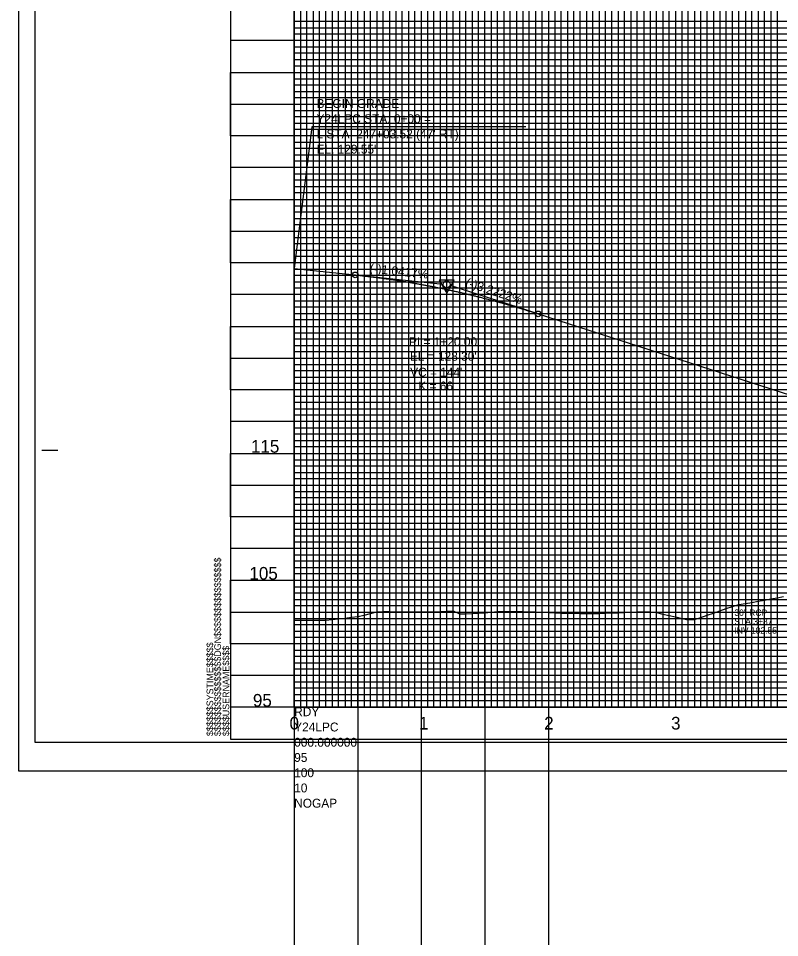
# Model space of a CAD drawing. Extents: x 2345490 to 2436403, y 465165 to 573888.
# Drawn here: x 2410678 to 2411277, y 523025 to 523748 of the extents above; entities that cross this region are included whole.
import ezdxf

# ---------------------------------------------------------------- set-up
doc = ezdxf.new("R2010")
doc.units = 0
for name, color, linetype in [('Old_Level_1', 7, 'Continuous'), ('Old_Level_18', 7, 'Continuous'), ('Old_Level_2', 7, 'Continuous'), ('Old_Level_3', 7, 'Continuous'), ('Old_Level_40', 7, 'Continuous'), ('Old_Level_41', 7, 'Continuous'), ('Old_Level_42', 7, 'Continuous'), ('Old_Level_43', 7, 'Continuous'), ('Old_Level_50', 7, 'Continuous'), ('Old_Level_51', 7, 'Continuous'), ('Old_Level_52', 7, 'Continuous'), ('Old_Level_62', 7, 'Continuous'), ('Old_Level_63', 7, 'Continuous')]:
    doc.layers.add(name, color=color, linetype=linetype)

msp = doc.modelspace()

# ---------------------------------------------------------------- linework, layer by layer
at = {"layer": 'Old_Level_1'}
msp.add_lwpolyline([(2410895.325, 523274.6675), (2410900.325, 523274.6325), (2410905.325, 523274.59725), (2410910.325, 523274.56125), (2410915.325, 523274.5245), (2410920.325, 523274.53525), (2410925.325, 523275.05275), (2410930.325, 523275.65025), (2410935.325, 523276.24575), (2410940.325, 523276.839), (2410945.325, 523277.4295), (2410950.325, 523278.501), (2410955.325, 523279.87925), (2410960.325, 523281.09575), (2410965.325, 523281.2845), (2410970.325, 523281.28375), (2410975.325, 523281.26525), (2410980.325, 523281.25025), (2410985.325, 523281.23875), (2410990.325, 523281.23125), (2410995.325, 523281.22775), (2411000.325, 523281.2285), (2411005.325, 523281.23375), (2411010.325, 523281.31075), (2411015.325, 523281.62125), (2411020.325, 523281.93025), (2411025.325, 523279.56475), (2411030.325, 523279.48925), (2411035.325, 523279.77975), (2411040.325, 523280.10525), (2411045.325, 523280.4675), (2411050.325, 523280.867), (2411055.325, 523281.3055), (2411060.325, 523281.60625), (2411065.325, 523281.5265), (2411070.325, 523281.44175), (2411075.325, 523281.3515), (2411080.325, 523281.24825), (2411085.325, 523281.04375), (2411090.325, 523280.8345), (2411095.325, 523280.62025), (2411100.325, 523280.401), (2411105.325, 523280.17675), (2411110.325, 523280.058), (2411115.325, 523280.009), (2411120.325, 523279.95725), (2411125.325, 523279.90275), (2411130.325, 523279.8455), (2411135.325, 523279.7855), (2411140.325, 523279.97425), (2411145.325, 523280.24075), (2411150.325, 523280.4725), (2411155.325, 523280.71125), (2411160.325, 523280.95725), (2411165.325, 523281.2105), (2411170.325, 523281.39525), (2411175.325, 523281.234), (2411180.325, 523280.5065), (2411185.325, 523279.378), (2411190.325, 523278.26325), (2411195.325, 523277.163), (2411200.325, 523276.01325), (2411205.325, 523274.81025), (2411210.325, 523275.07525), (2411215.325, 523276.74475), (2411220.325, 523278.4395), (2411225.325, 523280.15925), (2411230.325, 523281.90325), (2411235.325, 523283.67075), (2411240.325, 523285.4615), (2411245.325, 523286.84525), (2411250.325, 523287.71675), (2411255.325, 523288.597), (2411260.325, 523289.48575), (2411265.325, 523290.38325), (2411270.325, 523291.28875), (2411275.325, 523292.202), (2411280.325, 523293.123)], dxfattribs=at)
at = {"layer": 'Old_Level_18'}
msp.add_line((2410845.325, 523180.9495), (2410845.325, 523180.9495), dxfattribs=at)
msp.add_line((2410845.325, 523180.9495), (2410845.325, 523180.9495), dxfattribs=at)
msp.add_lwpolyline([(2412345.325, 524230.9495), (2410845.325, 524230.9495), (2410845.325, 523180.9495), (2412345.325, 523180.9495)], close=True, dxfattribs=at)
at = {"layer": 'Old_Level_2'}
for p, q in [((2410909.24625, 523663.1265), (2410895.325, 523551.4795)), ((2411077.71275, 523663.1265), (2410909.24625, 523663.1265)), ((2410895.325, 523551.4495), (2410943.325, 523546.4495)), ((2410943.325, 523546.4495), (2411012.59, 523539.2345)), ((2411087.325, 523515.7495), (2411017.9425, 523538.10625)), ((2411087.325, 523515.7495), (2411445.325, 523400.394))]:
    msp.add_line(p, q, dxfattribs=at)
msp.add_lwpolyline([(2411021.19225, 523542.332), (2411009.44975, 523542.3175), (2411015.33325, 523532.19925)], close=True, dxfattribs=at)
for centre, radius in [((2410943.325, 523546.4495), 2.25), ((2411015.325, 523538.9495), 2.75), ((2411087.325, 523515.7495), 2.25)]:
    msp.add_circle(centre, radius, dxfattribs=at)
msp.add_spline([(2410943.325, 523546.4495), (2410946.205, 523546.14325), (2410949.085, 523545.8245), (2410951.965, 523545.493), (2410954.845, 523545.14925), (2410957.725, 523544.7925), (2410960.605, 523544.4235), (2410963.485, 523544.042), (2410966.365, 523543.64775), (2410969.245, 523543.241), (2410972.125, 523542.8215), (2410975.005, 523542.38975), (2410977.885, 523541.94525), (2410980.765, 523541.48825), (2410983.645, 523541.01875), (2410986.525, 523540.5365), (2410989.405, 523540.042), (2410992.285, 523539.53475), (2410995.165, 523539.015), (2410998.045, 523538.4825), (2411000.925, 523537.9375), (2411003.805, 523537.38025), (2411006.685, 523536.81), (2411009.565, 523536.2275), (2411012.445, 523535.63225), (2411015.325, 523535.0245), (2411018.205, 523534.40425), (2411021.085, 523533.7715), (2411023.965, 523533.126), (2411026.845, 523532.46825), (2411029.725, 523531.7975), (2411032.605, 523531.1145), (2411035.485, 523530.419), (2411038.365, 523529.71075), (2411041.245, 523528.99), (2411044.125, 523528.2565), (2411047.005, 523527.51075), (2411049.885, 523526.75225), (2411052.765, 523525.98125), (2411055.645, 523525.19775), (2411058.525, 523524.4015), (2411061.405, 523523.593), (2411064.285, 523522.77175), (2411067.165, 523521.938), (2411070.045, 523521.0915), (2411072.925, 523520.2325), (2411075.805, 523519.36125), (2411078.685, 523518.477), (2411081.565, 523517.5805), (2411084.445, 523516.67125), (2411087.325, 523515.7495)], degree=3, dxfattribs=at)
at = {"layer": 'Old_Level_40'}
msp.add_line((2410845.325, 523180.9495), (2410845.325, 523180.9495), dxfattribs=at)
msp.add_line((2410845.325, 523180.9495), (2410845.325, 523180.9495), dxfattribs=at)
msp.add_line((2410845.325, 523180.9495), (2410845.325, 523180.9495), dxfattribs=at)
msp.add_line((2410845.325, 523180.9495), (2410845.325, 523180.9495), dxfattribs=at)
at = {"layer": 'Old_Level_41'}
for p, q in [((2410696.825, 523408.4495), (2410709.325, 523408.4495)), ((2412345.325, 523205.9495), (2410845.325, 523205.9495))]:
    msp.add_line(p, q, dxfattribs=at)
for points in [[(2410845.325, 524230.9495), (2410895.325, 524230.9495), (2410895.325, 523205.9495), (2410945.325, 523205.9495), (2410945.325, 524230.9495), (2410995.325, 524230.9495), (2410995.325, 523205.9495), (2411045.325, 523205.9495), (2411045.325, 524230.9495), (2411095.325, 524230.9495), (2411095.325, 523205.9495), (2411145.325, 523205.9495), (2411145.325, 524230.9495), (2411195.325, 524230.9495), (2411195.325, 523205.9495), (2411245.325, 523205.9495), (2411245.325, 524230.9495), (2411295.325, 524230.9495)], [(2410920.325, 523205.9495), (2410920.325, 524230.9495), (2410970.325, 524230.9495), (2410970.325, 523205.9495), (2411020.325, 523205.9495), (2411020.325, 524230.9495), (2411070.325, 524230.9495), (2411070.325, 523205.9495), (2411120.325, 523205.9495), (2411120.325, 524230.9495), (2411170.325, 524230.9495), (2411170.325, 523205.9495), (2411220.325, 523205.9495), (2411220.325, 524230.9495), (2411270.325, 524230.9495), (2411270.325, 523205.9495), (2411320.325, 523205.9495)], [(2412345.325, 523730.9495), (2410845.325, 523730.9495), (2410845.325, 523680.9495), (2412345.325, 523680.9495)], [(2412345.325, 523630.9495), (2410845.325, 523630.9495), (2410845.325, 523580.9495), (2412345.325, 523580.9495)], [(2412345.325, 523555.9495), (2410845.325, 523555.9495), (2410845.325, 523605.9495), (2412345.325, 523605.9495)], [(2412345.325, 523530.9495), (2410845.325, 523530.9495), (2410845.325, 523480.9495), (2412345.325, 523480.9495)], [(2412345.325, 523455.9495), (2410845.325, 523455.9495), (2410845.325, 523505.9495), (2412345.325, 523505.9495)], [(2412345.325, 523430.9495), (2410845.325, 523430.9495), (2410845.325, 523380.9495), (2412345.325, 523380.9495)], [(2412345.325, 523330.9495), (2410845.325, 523330.9495), (2410845.325, 523280.9495), (2412345.325, 523280.9495)], [(2412345.325, 523255.9495), (2410845.325, 523255.9495), (2410845.325, 523305.9495), (2412345.325, 523305.9495)], [(2412345.325, 523230.9495), (2410845.325, 523230.9495)], [(2410882.825, 523180.9495), (2410882.825, 523180.9495)]]:
    msp.add_lwpolyline(points, dxfattribs=at)
at = {"layer": 'Old_Level_42'}
for points in [[(2412345.325, 523655.9495), (2410845.325, 523655.9495), (2410845.325, 523705.9495), (2412345.325, 523705.9495)], [(2412345.325, 523355.9495), (2410845.325, 523355.9495), (2410845.325, 523405.9495), (2412345.325, 523405.9495)]]:
    msp.add_lwpolyline(points, dxfattribs=at)
at = {"layer": 'Old_Level_43'}
for points in [[(2410900.325, 524230.9495), (2410900.325, 523205.9495), (2410905.325, 523205.9495), (2410905.325, 524230.9495)], [(2410910.325, 524230.9495), (2410910.325, 523205.9495), (2410915.325, 523205.9495), (2410915.325, 524230.9495)], [(2410925.325, 524230.9495), (2410925.325, 523205.9495), (2410930.325, 523205.9495), (2410930.325, 524230.9495)], [(2410935.325, 524230.9495), (2410935.325, 523205.9495), (2410940.325, 523205.9495), (2410940.325, 524230.9495)], [(2410950.325, 524230.9495), (2410950.325, 523205.9495), (2410955.325, 523205.9495), (2410955.325, 524230.9495)], [(2410960.325, 524230.9495), (2410960.325, 523205.9495), (2410965.325, 523205.9495), (2410965.325, 524230.9495)], [(2410975.325, 524230.9495), (2410975.325, 523205.9495), (2410980.325, 523205.9495), (2410980.325, 524230.9495)], [(2410985.325, 524230.9495), (2410985.325, 523205.9495), (2410990.325, 523205.9495), (2410990.325, 524230.9495)], [(2411000.325, 524230.9495), (2411000.325, 523205.9495), (2411005.325, 523205.9495), (2411005.325, 524230.9495)], [(2411010.325, 524230.9495), (2411010.325, 523205.9495), (2411015.325, 523205.9495), (2411015.325, 524230.9495)], [(2411025.325, 524230.9495), (2411025.325, 523205.9495), (2411030.325, 523205.9495), (2411030.325, 524230.9495)], [(2411035.325, 524230.9495), (2411035.325, 523205.9495), (2411040.325, 523205.9495), (2411040.325, 524230.9495)], [(2411050.325, 524230.9495), (2411050.325, 523205.9495), (2411055.325, 523205.9495), (2411055.325, 524230.9495)], [(2411060.325, 523205.9495), (2411065.325, 523205.9495), (2411065.325, 524230.9495)], [(2411060.325, 524230.9495), (2411060.325, 523205.9495)], [(2411075.325, 524230.9495), (2411075.325, 523205.9495), (2411080.325, 523205.9495), (2411080.325, 524230.9495)], [(2411085.325, 524230.9495), (2411085.325, 523205.9495), (2411090.325, 523205.9495), (2411090.325, 524230.9495)], [(2411100.325, 524230.9495), (2411100.325, 523205.9495), (2411105.325, 523205.9495), (2411105.325, 524230.9495)], [(2411110.325, 524230.9495), (2411110.325, 523205.9495), (2411115.325, 523205.9495), (2411115.325, 524230.9495)], [(2411125.325, 524230.9495), (2411125.325, 523205.9495), (2411130.325, 523205.9495), (2411130.325, 524230.9495)], [(2411135.325, 524230.9495), (2411135.325, 523205.9495), (2411140.325, 523205.9495), (2411140.325, 524230.9495)], [(2411150.325, 524230.9495), (2411150.325, 523205.9495), (2411155.325, 523205.9495), (2411155.325, 524230.9495)], [(2411160.325, 524230.9495), (2411160.325, 523205.9495), (2411165.325, 523205.9495), (2411165.325, 524230.9495)], [(2411175.325, 524230.9495), (2411175.325, 523205.9495), (2411180.325, 523205.9495), (2411180.325, 524230.9495)], [(2411185.325, 524230.9495), (2411185.325, 523205.9495), (2411190.325, 523205.9495), (2411190.325, 524230.9495)], [(2411200.325, 524230.9495), (2411200.325, 523205.9495), (2411205.325, 523205.9495), (2411205.325, 524230.9495)], [(2411210.325, 524230.9495), (2411210.325, 523205.9495), (2411215.325, 523205.9495), (2411215.325, 524230.9495)], [(2411225.325, 524230.9495), (2411225.325, 523205.9495), (2411240.325, 523205.9495), (2411240.325, 524230.9495)], [(2411230.325, 524230.9495), (2411230.325, 523205.9495), (2411235.325, 523205.9495), (2411235.325, 524230.9495)], [(2411230.325, 524230.3495), (2411230.325, 523205.9495), (2411235.325, 523205.9495), (2411235.325, 524230.3495)], [(2411250.325, 524230.9495), (2411250.325, 523205.9495), (2411255.325, 523205.9495), (2411255.325, 524230.9495)], [(2411260.325, 524230.9495), (2411260.325, 523205.9495), (2411265.325, 523205.9495), (2411265.325, 524230.9495)], [(2411275.325, 524230.9495), (2411275.325, 523205.9495), (2411280.325, 523205.9495)], [(2412295.325, 523745.9495), (2410895.325, 523745.9495), (2410895.325, 523740.9495), (2412295.325, 523740.9495)], [(2412295.325, 523735.9495), (2410895.325, 523735.9495), (2410895.325, 523725.9495), (2412295.325, 523725.9495)], [(2412295.325, 523720.9495), (2410895.325, 523720.9495), (2410895.325, 523715.9495), (2412295.325, 523715.9495)], [(2412295.325, 523710.9495), (2410895.325, 523710.9495)], [(2410895.325, 523700.9495), (2412295.325, 523700.9495)], [(2412295.325, 523695.9495), (2410895.325, 523695.9495), (2410895.325, 523690.9495), (2412295.325, 523690.9495)], [(2412295.325, 523685.9495), (2410895.325, 523685.9495), (2410895.325, 523675.9495), (2412295.325, 523675.9495)], [(2412295.325, 523670.9495), (2410895.325, 523670.9495), (2410895.325, 523665.9495), (2412295.325, 523665.9495)], [(2412295.325, 523660.9495), (2410895.325, 523660.9495), (2410895.325, 523650.9495), (2412295.325, 523650.9495)], [(2412295.325, 523645.9495), (2410895.325, 523645.9495), (2410895.325, 523640.9495), (2412295.325, 523640.9495)], [(2412295.325, 523635.9495), (2410895.325, 523635.9495), (2410895.325, 523625.9495), (2412295.325, 523625.9495)], [(2412295.325, 523620.9495), (2410895.325, 523620.9495), (2410895.325, 523615.9495), (2412295.325, 523615.9495)], [(2412295.325, 523610.9495), (2410895.325, 523610.9495), (2410895.325, 523600.9495), (2412295.325, 523600.9495)], [(2412295.325, 523595.9495), (2410895.325, 523595.9495), (2410895.325, 523590.9495), (2412295.325, 523590.9495)], [(2412295.325, 523585.9495), (2410895.325, 523585.9495), (2410895.325, 523575.9495), (2412295.325, 523575.9495)], [(2412295.325, 523570.9495), (2410895.325, 523570.9495), (2410895.325, 523565.9495), (2412295.325, 523565.9495)], [(2412295.325, 523560.9495), (2410895.325, 523560.9495), (2410895.325, 523550.9495), (2412295.325, 523550.9495)], [(2412295.325, 523545.9495), (2410895.325, 523545.9495), (2410895.325, 523540.9495), (2412295.325, 523540.9495)], [(2412295.325, 523535.9495), (2410895.325, 523535.9495), (2410895.325, 523525.9495), (2412295.325, 523525.9495)], [(2412295.325, 523520.9495), (2410895.325, 523520.9495), (2410895.325, 523515.9495), (2412295.325, 523515.9495)], [(2412295.325, 523510.9495), (2410895.325, 523510.9495), (2410895.325, 523500.9495), (2412295.325, 523500.9495)], [(2412295.325, 523495.9495), (2410895.325, 523495.9495), (2410895.325, 523490.9495), (2412295.325, 523490.9495)], [(2412295.325, 523485.9495), (2410895.325, 523485.9495), (2410895.325, 523475.9495), (2412295.325, 523475.9495)], [(2412295.325, 523470.9495), (2410895.325, 523470.9495), (2410895.325, 523465.9495), (2412295.325, 523465.9495)], [(2412295.325, 523460.9495), (2410895.325, 523460.9495), (2410895.325, 523450.9495), (2412295.325, 523450.9495)], [(2412295.325, 523445.9495), (2410895.325, 523445.9495), (2410895.325, 523440.9495), (2412295.325, 523440.9495)], [(2412295.325, 523435.9495), (2410895.325, 523435.9495), (2410895.325, 523425.9495), (2412295.325, 523425.9495)], [(2412295.325, 523420.9495), (2410895.325, 523420.9495), (2410895.325, 523415.9495), (2412295.325, 523415.9495)], [(2412295.325, 523410.9495), (2410895.325, 523410.9495)], [(2410895.325, 523400.9495), (2412295.325, 523400.9495)], [(2412295.325, 523395.9495), (2410895.325, 523395.9495), (2410895.325, 523390.9495), (2412295.325, 523390.9495)], [(2412295.325, 523385.9495), (2410895.325, 523385.9495)], [(2410895.325, 523375.9495), (2412295.325, 523375.9495)], [(2412295.325, 523370.9495), (2410895.325, 523370.9495), (2410895.325, 523365.9495), (2412295.325, 523365.9495)], [(2412295.325, 523360.9495), (2410895.325, 523360.9495), (2410895.325, 523350.9495), (2412295.325, 523350.9495)], [(2412295.325, 523345.9495), (2410895.325, 523345.9495), (2410895.325, 523340.9495), (2412295.325, 523340.9495)], [(2412295.325, 523335.9495), (2410895.325, 523335.9495), (2410895.325, 523325.9495), (2412295.325, 523325.9495)], [(2412295.325, 523320.9495), (2410895.325, 523320.9495), (2410895.325, 523315.9495), (2412295.325, 523315.9495)], [(2412295.325, 523310.9495), (2410895.325, 523310.9495), (2410895.325, 523300.9495), (2412295.325, 523300.9495)], [(2412295.325, 523295.9495), (2410895.325, 523295.9495), (2410895.325, 523290.9495), (2412295.325, 523290.9495)], [(2412295.325, 523285.9495), (2410895.325, 523285.9495), (2410895.325, 523275.9495), (2412295.325, 523275.9495)], [(2412295.325, 523270.9495), (2410895.325, 523270.9495), (2410895.325, 523265.9495), (2412295.325, 523265.9495)], [(2412295.325, 523260.9495), (2410895.325, 523260.9495), (2410895.325, 523250.9495), (2412295.325, 523250.9495)], [(2412295.325, 523245.9495), (2410895.325, 523245.9495), (2410895.325, 523240.9495), (2412295.325, 523240.9495)], [(2412295.325, 523235.9495), (2410895.325, 523235.9495), (2410895.325, 523225.9495), (2412295.325, 523225.9495)], [(2412295.325, 523220.9495), (2410895.325, 523220.9495), (2410895.325, 523215.9495), (2412295.325, 523215.9495)], [(2412295.325, 523210.9495), (2410895.325, 523210.9495)]]:
    msp.add_lwpolyline(points, dxfattribs=at)
at = {"layer": 'Old_Level_50'}
msp.add_line((2410678.325, 523155.9495), (2410678.325, 523155.9495), dxfattribs=at)
msp.add_lwpolyline([(2412357.825, 524233.4995), (2410691.325, 524233.4995), (2410691.325, 523178.3995), (2412357.825, 523178.3995)], close=True, dxfattribs=at)
at = {"layer": 'Old_Level_51'}
msp.add_lwpolyline([(2412362.325, 524255.9495), (2410678.325, 524255.9495), (2410678.325, 523155.9495), (2412362.325, 523155.9495)], close=True, dxfattribs=at)
at = {"layer": 'Old_Level_52'}
msp.add_line((2410691.325, 523178.3995), (2410691.325, 523178.3995), dxfattribs=at)
at = {"layer": 'Old_Level_63'}
for p, q in [((2410895.325, 523205.9495), (2410895.325, 525705.9495)), ((2411045.325, 523528.9595), (2411045.325, 523727.5905)), ((2411095.325, 523514.9795), (2411095.325, 523727.5905)), ((2410895.325, 523551.4795), (2410895.325, 522887.531)), ((2410945.325, 523546.2195), (2410945.325, 522887.491)), ((2410995.325, 523538.9695), (2410995.325, 522887.491)), ((2411045.325, 523526.4295), (2411045.325, 522887.491)), ((2411095.325, 523507.1595), (2411095.325, 522887.491)), ((2410895.325, 523205.9495), (2412133.8245, 523205.9495)), ((2410895.325, 523205.9495), (2410895.325, 520705.9495))]:
    msp.add_line(p, q, dxfattribs=at)

# ---------------------------------------------------------------- texts
at = {"layer": 'Old_Level_2'}
for s, height, p in [('BEGIN GRADE', 7.0000005, (2410912.919, 523677.94475)), ('Y24LPC STA. 0+00 =', 7.0000005, (2410912.919, 523665.94475)), ("L STA. 247+03.52 (47' RT)", 7.0000005, (2410912.919, 523653.94475)), ("EL. 129.55'", 7.0000005, (2410912.919, 523641.94475)), ('PI = 1+20.00', 7.0000005, (2410985.6525, 523490.34875)), ("EL = 128.30'", 7.0000005, (2410986.363, 523478.87575)), ("VC = 144'", 7.000001, (2410986.55725, 523466.3585)), ('K = 66', 7.000001, (2410992.95025, 523455.48875))]:
    msp.add_text(s, height=height, dxfattribs=at).set_placement(p)
for s, rotation, p in [('(-)1.0417%', 354.05313611, (2410954.47475, 523548.3045)), ('(-)3.2222%', 342.13990556, (2411029.455, 523537.5485))]:
    msp.add_text(s, height=7.000001, rotation=rotation, dxfattribs=at).set_placement(p)
at = {"layer": 'Old_Level_3'}
for s, p in [('30" RCP', (2411241.70895, 523277.99468)), ('STA 3+87', (2411241.70896, 523270.99468)), ('INV 102.55', (2411241.70896, 523263.99468))]:
    msp.add_text(s, height=4.999999, rotation=0.00003889, dxfattribs=at).set_placement(p)
at = {"layer": 'Old_Level_41'}
for s, p in [('$$$$$$$$$$$$$$$$DGN$$$$$$$$$$$$$$$$', (2410837.675, 523183.312)), ('$$$$$$SYSTIME$$$$$', (2410831.625, 523183.312)), ('$$$$USERNAME$$$$', (2410844.25, 523183.3245))]:
    msp.add_text(s, height=5.25, rotation=90, dxfattribs=at).set_placement(p)
at = {"layer": 'Old_Level_62'}
for s, height, p in [('115', 10.000001, (2410861.3085, 523406.4495)), ('105', 10.000001, (2410860.1115, 523306.4495)), ('95', 10.000001, (2410862.869, 523206.4495)), ('0', 10, (2410891.666, 523188.4495)), ('1', 10, (2410993.5055, 523188.4495)), ('2', 10, (2411092.054, 523188.4495)), ('3', 10, (2411191.88875, 523188.4495))]:
    msp.add_text(s, height=height, dxfattribs=at).set_placement(p)
at = {"layer": 'Old_Level_63'}
for s, p in [('RDY', (2410895.325, 523198.9495)), ('Y24LPC', (2410895.325, 523186.9495)), ('000.000000', (2410895.325, 523174.9495)), ('95', (2410895.325, 523162.9495)), ('100', (2410895.325, 523150.9495)), ('10', (2410895.325, 523138.9495)), ('NOGAP', (2410895.325, 523126.9495))]:
    msp.add_text(s, height=7.000001, dxfattribs=at).set_placement(p)

doc.saveas('drawing.dxf')
